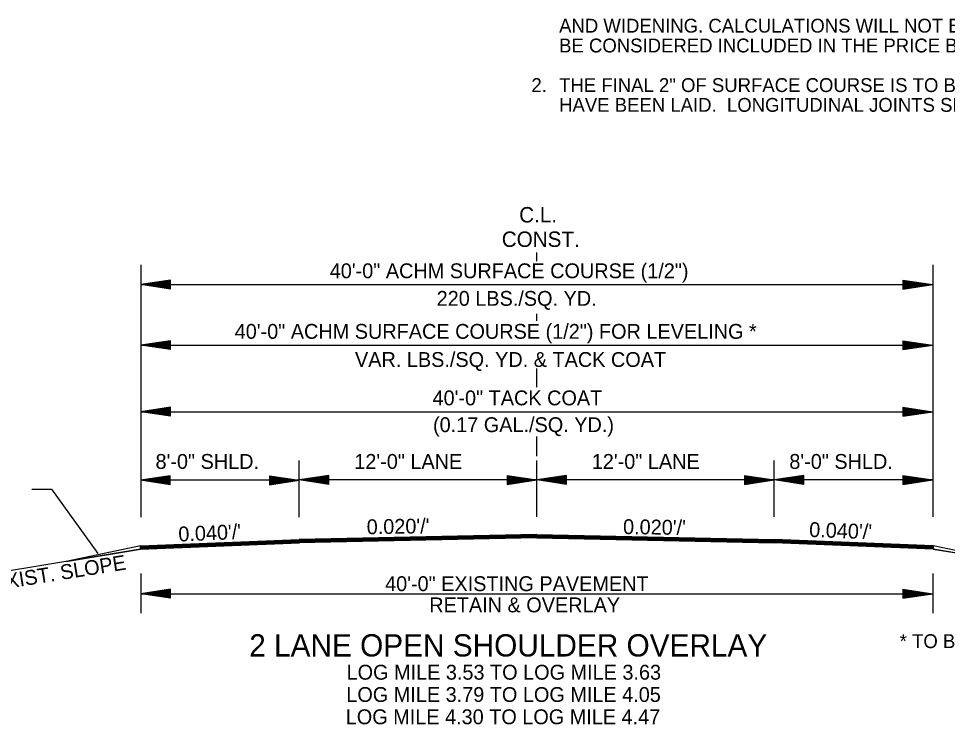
# Model space of a CAD drawing. Extents: x 544199 to 1930787, y -1968972 to 596640.
# Drawn here: x 551718.3 to 552187.5, y -1946877.6 to -1946521.1 of the extents above; entities that cross this region are included whole.
import ezdxf

# ---------------------------------------------------------------- set-up
doc = ezdxf.new("R2010")
doc.units = 0
for name, color, linetype in [('R_Border Notes', 7, 'Continuous'), ('R_Border Prem', 7, 'Continuous'), ('R_Draft', 7, 'Continuous')]:
    doc.layers.add(name, color=color, linetype=linetype)

msp = doc.modelspace()

# ---------------------------------------------------------------- linework, layer by layer
at = {"layer": 'R_Draft'}
for p, q in [((551980.07, -1946643.68), (551980.07, -1946639.27)), ((551780.07, -1946645.52), (551780.07, -1946772.95)), ((551795.07, -1946653.19), (551780.07, -1946655.44)), ((551780.07, -1946655.44), (552180.07, -1946655.44)), ((551795.07, -1946657.69), (551780.07, -1946655.44)), ((551795.07, -1946653.56), (551782.58, -1946655.44)), ((551795.07, -1946657.31), (551782.58, -1946655.44)), ((551795.07, -1946653.95), (551785.16, -1946655.44)), ((551795.07, -1946656.93), (551785.16, -1946655.44)), ((551795.07, -1946654.32), (551787.65, -1946655.44)), ((551795.07, -1946656.56), (551787.65, -1946655.44)), ((551795.07, -1946654.7), (551790.2, -1946655.44)), ((551795.07, -1946656.17), (551790.2, -1946655.44)), ((551795.07, -1946655.09), (551792.7, -1946655.44)), ((551795.07, -1946655.79), (551792.7, -1946655.44)), ((551795.07, -1946657.69), (551795.07, -1946653.19)), ((552165.07, -1946653.19), (552180.07, -1946655.44)), ((552165.07, -1946653.19), (552165.07, -1946657.69)), ((552165.07, -1946653.56), (552177.57, -1946655.44)), ((552165.07, -1946653.95), (552174.99, -1946655.44)), ((552165.07, -1946654.32), (552172.49, -1946655.44)), ((552165.07, -1946654.71), (552169.95, -1946655.44)), ((552165.07, -1946655.09), (552167.44, -1946655.44)), ((552165.07, -1946657.69), (552180.07, -1946655.44)), ((552165.07, -1946656.17), (552169.95, -1946655.44)), ((552165.07, -1946656.93), (552174.99, -1946655.44)), ((552165.07, -1946657.31), (552177.57, -1946655.44)), ((552165.07, -1946656.56), (552172.49, -1946655.44)), ((552165.07, -1946655.79), (552167.44, -1946655.44)), ((551980.07, -1946673.81), (551980.07, -1946670.14)), ((551795.07, -1946683.79), (551780.07, -1946686.04)), ((551795.07, -1946688.29), (551795.07, -1946683.79)), ((552165.07, -1946683.79), (552180.07, -1946686.04)), ((552165.07, -1946683.79), (552165.07, -1946688.29)), ((551780.07, -1946686.04), (552180.07, -1946686.04)), ((551795.07, -1946688.29), (551780.07, -1946686.04)), ((551795.07, -1946684.16), (551782.58, -1946686.04)), ((551795.07, -1946687.91), (551782.58, -1946686.04)), ((551795.07, -1946684.54), (551785.16, -1946686.04)), ((551795.07, -1946687.53), (551785.16, -1946686.04)), ((551795.07, -1946684.92), (551787.65, -1946686.04)), ((551795.07, -1946687.15), (551787.65, -1946686.04)), ((551795.07, -1946685.3), (551790.2, -1946686.04)), ((551795.07, -1946686.76), (551790.2, -1946686.04)), ((551795.07, -1946685.68), (551792.7, -1946686.04)), ((551795.07, -1946686.39), (551792.7, -1946686.04)), ((552165.07, -1946684.16), (552177.57, -1946686.04)), ((552165.07, -1946684.54), (552174.99, -1946686.04)), ((552165.07, -1946684.92), (552172.49, -1946686.04)), ((552165.07, -1946685.31), (552169.95, -1946686.04)), ((552165.07, -1946685.68), (552167.44, -1946686.04)), ((552165.07, -1946688.29), (552180.07, -1946686.04)), ((552165.07, -1946686.77), (552169.95, -1946686.04)), ((552165.07, -1946687.53), (552174.99, -1946686.04)), ((552165.07, -1946687.91), (552177.57, -1946686.04)), ((552165.07, -1946687.15), (552172.49, -1946686.04)), ((552165.07, -1946686.39), (552167.44, -1946686.04)), ((551980.07, -1946707.17), (551980.07, -1946697.86)), ((551795.07, -1946717.39), (551780.07, -1946719.64)), ((551780.07, -1946719.64), (552180.07, -1946719.64)), ((551795.07, -1946721.89), (551780.07, -1946719.64)), ((551795.07, -1946717.76), (551782.58, -1946719.64)), ((551795.07, -1946721.51), (551782.58, -1946719.64)), ((551795.07, -1946718.14), (551785.16, -1946719.64)), ((551795.07, -1946721.13), (551785.16, -1946719.64)), ((551795.07, -1946718.52), (551787.65, -1946719.64)), ((551795.07, -1946720.75), (551787.65, -1946719.64)), ((551795.07, -1946718.9), (551790.2, -1946719.64)), ((551795.07, -1946720.36), (551790.2, -1946719.64)), ((551795.07, -1946719.28), (551792.7, -1946719.64)), ((551795.07, -1946719.99), (551792.7, -1946719.64)), ((551795.07, -1946721.89), (551795.07, -1946717.39)), ((552165.07, -1946717.39), (552180.07, -1946719.64)), ((552165.07, -1946717.39), (552165.07, -1946721.89)), ((552165.07, -1946717.76), (552177.57, -1946719.64)), ((552165.07, -1946718.14), (552174.99, -1946719.64)), ((552165.07, -1946718.52), (552172.49, -1946719.64)), ((552165.07, -1946718.91), (552169.95, -1946719.64)), ((552165.07, -1946719.28), (552167.44, -1946719.64)), ((552165.07, -1946721.89), (552180.07, -1946719.64)), ((552165.07, -1946720.37), (552169.95, -1946719.64)), ((552165.07, -1946721.13), (552174.99, -1946719.64)), ((552165.07, -1946721.51), (552177.57, -1946719.64)), ((552165.07, -1946720.75), (552172.49, -1946719.64)), ((552165.07, -1946719.99), (552167.44, -1946719.64)), ((551980.07, -1946742.1), (551980.07, -1946732.23)), ((551860.07, -1946772.78), (551860.07, -1946744.23)), ((551860.07, -1946772.95), (551860.07, -1946744.23)), ((551980.07, -1946772.78), (551980.07, -1946744.23)), ((552100, -1946754.12), (552100, -1946744.23)), ((552100, -1946772.78), (552100, -1946744.23)), ((551794.81, -1946752.04), (551779.81, -1946754.29)), ((551794.81, -1946756.54), (551779.81, -1946754.29)), ((551860.07, -1946754.29), (551780.07, -1946754.29)), ((551794.81, -1946752.41), (551782.32, -1946754.29)), ((551794.81, -1946756.16), (551782.32, -1946754.29)), ((551794.81, -1946752.8), (551784.9, -1946754.29)), ((551794.81, -1946755.78), (551784.9, -1946754.29)), ((551794.81, -1946753.17), (551787.39, -1946754.29)), ((551794.81, -1946755.41), (551787.39, -1946754.29)), ((551794.81, -1946753.55), (551789.94, -1946754.29)), ((551794.81, -1946755.02), (551789.94, -1946754.29)), ((551794.81, -1946753.94), (551792.44, -1946754.29)), ((551794.81, -1946754.64), (551792.44, -1946754.29)), ((551794.81, -1946756.54), (551794.81, -1946752.04)), ((551845.07, -1946752.04), (551860.07, -1946754.29)), ((551845.07, -1946752.04), (551845.07, -1946756.54)), ((551845.07, -1946752.41), (551857.57, -1946754.29)), ((551845.07, -1946752.8), (551854.99, -1946754.29)), ((551845.07, -1946753.17), (551852.49, -1946754.29)), ((551845.07, -1946753.56), (551849.95, -1946754.29)), ((551845.07, -1946753.94), (551847.44, -1946754.29)), ((551845.07, -1946756.54), (551860.07, -1946754.29)), ((551845.07, -1946755.02), (551849.95, -1946754.29)), ((551845.07, -1946755.78), (551854.99, -1946754.29)), ((551845.07, -1946756.16), (551857.57, -1946754.29)), ((551845.07, -1946755.41), (551852.49, -1946754.29)), ((551845.07, -1946754.64), (551847.44, -1946754.29)), ((551875.07, -1946751.87), (551860.07, -1946754.12)), ((551980.07, -1946754.12), (551860.07, -1946754.12)), ((551875.07, -1946756.37), (551860.07, -1946754.12)), ((551875.07, -1946752.24), (551862.58, -1946754.12)), ((551875.07, -1946755.99), (551862.58, -1946754.12)), ((551875.07, -1946752.63), (551865.16, -1946754.12)), ((551875.07, -1946755.61), (551865.16, -1946754.12)), ((551875.07, -1946753), (551867.65, -1946754.12)), ((551875.07, -1946755.24), (551867.65, -1946754.12)), ((551875.07, -1946753.38), (551870.2, -1946754.12)), ((551875.07, -1946754.85), (551870.2, -1946754.12)), ((551875.07, -1946753.77), (551872.7, -1946754.12)), ((551875.07, -1946754.47), (551872.7, -1946754.12)), ((551875.07, -1946756.37), (551875.07, -1946751.87)), ((551965.07, -1946751.87), (551980.07, -1946754.12)), ((551965.07, -1946751.87), (551965.07, -1946756.37)), ((551965.07, -1946752.24), (551977.57, -1946754.12)), ((551965.07, -1946752.63), (551974.99, -1946754.12)), ((551965.07, -1946753), (551972.49, -1946754.12)), ((551965.07, -1946753.39), (551969.95, -1946754.12)), ((551965.07, -1946753.77), (551967.44, -1946754.12)), ((551965.07, -1946756.37), (551980.07, -1946754.12)), ((551965.07, -1946754.85), (551969.95, -1946754.12)), ((551965.07, -1946755.61), (551974.99, -1946754.12)), ((551965.07, -1946755.99), (551977.57, -1946754.12)), ((551965.07, -1946755.24), (551972.49, -1946754.12)), ((551965.07, -1946754.47), (551967.44, -1946754.12)), ((551995.07, -1946751.87), (551980.07, -1946754.12)), ((552100.07, -1946754.12), (551980.07, -1946754.12)), ((551995.07, -1946756.37), (551980.07, -1946754.12)), ((551995.07, -1946752.24), (551982.58, -1946754.12)), ((551995.07, -1946755.99), (551982.58, -1946754.12)), ((551995.07, -1946752.63), (551985.16, -1946754.12)), ((551995.07, -1946755.61), (551985.16, -1946754.12)), ((551995.07, -1946753), (551987.65, -1946754.12)), ((551995.07, -1946755.24), (551987.65, -1946754.12)), ((551995.07, -1946753.38), (551990.2, -1946754.12)), ((551995.07, -1946754.85), (551990.2, -1946754.12)), ((551995.07, -1946753.77), (551992.7, -1946754.12)), ((551995.07, -1946754.47), (551992.7, -1946754.12)), ((551995.07, -1946756.37), (551995.07, -1946751.87)), ((552085, -1946751.87), (552100, -1946754.12)), ((552085, -1946751.87), (552085, -1946756.37)), ((552085, -1946752.24), (552097.49, -1946754.12)), ((552085, -1946752.63), (552094.91, -1946754.12)), ((552085, -1946753), (552092.42, -1946754.12)), ((552085, -1946753.39), (552089.87, -1946754.12)), ((552085, -1946753.77), (552087.37, -1946754.12)), ((552085, -1946756.37), (552100, -1946754.12)), ((552085, -1946754.85), (552089.87, -1946754.12)), ((552085, -1946755.61), (552094.91, -1946754.12)), ((552085, -1946755.99), (552097.49, -1946754.12)), ((552085, -1946755.24), (552092.42, -1946754.12)), ((552085, -1946754.47), (552087.37, -1946754.12)), ((552115, -1946751.87), (552100, -1946754.12)), ((552100, -1946772.78), (552100, -1946754.12)), ((552115, -1946756.37), (552100, -1946754.12)), ((552180.07, -1946754.12), (552100.07, -1946754.12)), ((552115, -1946752.24), (552102.5, -1946754.12)), ((552115, -1946755.99), (552102.5, -1946754.12)), ((552115, -1946752.63), (552105.08, -1946754.12)), ((552115, -1946755.61), (552105.08, -1946754.12)), ((552115, -1946753), (552107.58, -1946754.12)), ((552115, -1946755.24), (552107.58, -1946754.12)), ((552115, -1946753.38), (552110.12, -1946754.12)), ((552115, -1946754.85), (552110.12, -1946754.12)), ((552115, -1946753.77), (552112.63, -1946754.12)), ((552115, -1946754.47), (552112.63, -1946754.12)), ((552115, -1946756.37), (552115, -1946751.87)), ((552165.07, -1946751.87), (552180.07, -1946754.12)), ((552165.07, -1946751.87), (552165.07, -1946756.37)), ((552165.07, -1946752.24), (552177.57, -1946754.12)), ((552165.07, -1946752.63), (552174.99, -1946754.12)), ((552165.07, -1946753), (552172.49, -1946754.12)), ((552165.07, -1946753.39), (552169.95, -1946754.12)), ((552165.07, -1946753.77), (552167.44, -1946754.12)), ((552165.07, -1946756.37), (552180.07, -1946754.12)), ((552165.07, -1946754.85), (552169.95, -1946754.12)), ((552165.07, -1946755.61), (552174.99, -1946754.12)), ((552165.07, -1946755.99), (552177.57, -1946754.12)), ((552165.07, -1946755.24), (552172.49, -1946754.12)), ((552165.07, -1946754.47), (552167.44, -1946754.12)), ((551980.07, -1946781.72), (551860.07, -1946784.12)), ((551980.08, -1946782.02), (551860.08, -1946784.42)), ((551980.08, -1946782.32), (551860.08, -1946784.72)), ((551980.06, -1946782.32), (552100.06, -1946784.72)), ((551980.07, -1946781.72), (552100.07, -1946784.12)), ((551980.07, -1946782.02), (552100.07, -1946784.42)), ((551779.81, -1946787.34), (551860.07, -1946784.12)), ((551779.81, -1946787.64), (551860.08, -1946784.42)), ((551779.81, -1946787.94), (551860.1, -1946784.72)), ((551779.81, -1946788.24), (551860.11, -1946785.02)), ((551779.81, -1946788.54), (551860.12, -1946785.32)), ((551779.81, -1946788.84), (551860.13, -1946785.62)), ((551779.81, -1946789.04), (551860.14, -1946785.82)), ((551980.09, -1946782.62), (551860.09, -1946785.02)), ((551980.1, -1946782.92), (551860.1, -1946785.32)), ((551980.1, -1946783.22), (551860.1, -1946785.62)), ((551980.11, -1946783.42), (551860.11, -1946785.82)), ((551980.04, -1946783.22), (552100.04, -1946785.62)), ((551980.04, -1946783.42), (552100.04, -1946785.82)), ((551980.05, -1946782.62), (552100.05, -1946785.02)), ((551980.05, -1946782.92), (552100.05, -1946785.32)), ((552180.33, -1946789.04), (552100, -1946785.82)), ((552180.33, -1946788.84), (552100.01, -1946785.62)), ((552180.33, -1946788.54), (552100.02, -1946785.32)), ((552180.33, -1946788.24), (552100.04, -1946785.02)), ((552180.33, -1946787.94), (552100.05, -1946784.72)), ((552180.33, -1946787.64), (552100.06, -1946784.42)), ((552180.33, -1946787.34), (552100.07, -1946784.12)), ((551779.81, -1946789.04), (551679.74, -1946805.71)), ((551779.81, -1946787.34), (551742.32, -1946795.28)), ((551742.32, -1946795.28), (551779.81, -1946789.04)), ((551779.81, -1946789.04), (551779.81, -1946787.34)), ((551779.81, -1946789.04), (551779.81, -1946787.34)), ((551779.81, -1946789.04), (551779.81, -1946787.34)), ((551779.81, -1946789.04), (551779.81, -1946789.04)), ((552180.33, -1946789.04), (552180.33, -1946787.34)), ((552180.33, -1946787.34), (552180.33, -1946789.04)), ((552219.58, -1946795.57), (552180.33, -1946787.34)), ((552180.33, -1946787.34), (552180.33, -1946789.04)), ((552180.33, -1946789.04), (552180.33, -1946787.34)), ((552280.4, -1946805.71), (552180.33, -1946789.04)), ((552180.33, -1946789.04), (552180.33, -1946789.04)), ((552180.33, -1946789.04), (552219.58, -1946795.57)), ((551780.07, -1946801.33), (551780.07, -1946821.33)), ((552180.07, -1946801.33), (552180.07, -1946821.33)), ((551795.07, -1946809.33), (551780.07, -1946811.58)), ((551795.07, -1946809.71), (551782.58, -1946811.58)), ((551795.07, -1946810.09), (551785.16, -1946811.58)), ((551795.07, -1946810.47), (551787.65, -1946811.58)), ((551795.07, -1946813.83), (551795.07, -1946809.33)), ((552165.07, -1946809.33), (552180.07, -1946811.58)), ((552165.07, -1946809.33), (552165.07, -1946813.83)), ((552165.07, -1946809.71), (552177.57, -1946811.58)), ((552165.07, -1946810.09), (552174.99, -1946811.58)), ((552165.07, -1946810.47), (552172.49, -1946811.58)), ((551780.07, -1946811.58), (552180.07, -1946811.58)), ((551795.07, -1946813.83), (551780.07, -1946811.58)), ((551795.07, -1946813.46), (551782.58, -1946811.58)), ((551795.07, -1946813.08), (551785.16, -1946811.58)), ((551795.07, -1946812.7), (551787.65, -1946811.58)), ((551795.07, -1946810.85), (551790.2, -1946811.58)), ((551795.07, -1946812.31), (551790.2, -1946811.58)), ((551795.07, -1946811.23), (551792.7, -1946811.58)), ((551795.07, -1946811.94), (551792.7, -1946811.58)), ((552165.07, -1946810.86), (552169.95, -1946811.58)), ((552165.07, -1946811.23), (552167.44, -1946811.58)), ((552165.07, -1946813.83), (552180.07, -1946811.58)), ((552165.07, -1946812.32), (552169.95, -1946811.58)), ((552165.07, -1946813.08), (552174.99, -1946811.58)), ((552165.07, -1946813.46), (552177.57, -1946811.58)), ((552165.07, -1946812.7), (552172.49, -1946811.58)), ((552165.07, -1946811.94), (552167.44, -1946811.58))]:
    msp.add_line(p, q, dxfattribs=at)
for points in [[(552180.07, -1946645.52), (552180.07, -1946772.78)], [(551724.96, -1946758.8), (551734.96, -1946758.8), (551758.29, -1946791.29)]]:
    msp.add_lwpolyline(points, dxfattribs=at)

# ---------------------------------------------------------------- texts
at = {"layer": 'R_Border Notes'}
for s, p in [('AND WIDENING. CALCULATIONS WILL NOT BE PAID FOR DIRECTLY, BUT PAYMENT SHALL', (551991.36, -1946528.18)), ('BE CONSIDERED INCLUDED IN THE PRICE BID FOR THE VARIOUS PAY ITEMS.', (551991.36, -1946538.18)), ('2.', (551977.36, -1946558.18)), ('THE FINAL 2" OF SURFACE COURSE IS TO BE PLACED AFTER ALL OTHER COURSES', (551991.36, -1946558.18)), ('HAVE BEEN LAID.  LONGITUDINAL JOINTS SHALL BE AT LANE LINES.', (551991.36, -1946568.18))]:
    msp.add_text(s, height=7, dxfattribs=at).set_placement(p)
at = {"layer": 'R_Border Prem'}
msp.add_text('* TO BE USED IF AND WHERE DIRECTED BY THE ENGINEER.', height=7, dxfattribs=at).set_placement((552163.42, -1946839.04))
at = {"layer": 'R_Draft'}
for s, height, p in [('C.L.', 7.8, (551971.18, -1946624.07)), ('CONST.', 7.8, (551962.39, -1946636.43)), ('40\'-0" ACHM SURFACE COURSE (1/2")', 7.5, (551875.48, -1946652.22)), ('220 LBS./SQ. YD. ', 7.5, (551929.49, -1946666.16)), ('40\'-0" ACHM SURFACE COURSE (1/2") FOR LEVELING *', 7.5, (551827.47, -1946682.82)), ('VAR. LBS./SQ. YD. & TACK COAT', 7.5, (551888.24, -1946697.03)), ('40\'-0" TACK COAT', 7.5, (551927.42, -1946716.42)), ('(0.17 GAL./SQ. YD.)', 7.5, (551927.66, -1946729.96)), ('8\'-0" SHLD.', 7.5, (551787.46, -1946748.52)), ('12\'-0" LANE', 7.5, (551887.89, -1946748.52)), ('12\'-0" LANE', 7.5, (552007.85, -1946748.52)), ('8\'-0" SHLD.', 7.5, (552107.65, -1946748.52)), ('40\'-0" EXISTING PAVEMENT', 7.5, (551903.45, -1946810.26)), ('RETAIN & OVERLAY', 7.5, (551925.74, -1946820.98)), ('2 LANE OPEN SHOULDER OVERLAY', 11.25, (551834.8, -1946843.29)), ('LOG MILE 3.53 TO LOG MILE 3.63', 7.5, (551883.99, -1946854.99)), ('LOG MILE 3.79 TO LOG MILE 4.05', 7.5, (551883.87, -1946866.24)), ('LOG MILE 4.30 TO LOG MILE 4.47', 7.5, (551883.58, -1946877.49))]:
    msp.add_text(s, height=height, dxfattribs=at).set_placement(p)
for s, rotation, p in [("0.040'/'", 2.448, (551799.16, -1946785.24)), ("0.020'/'", 0.8719, (551894.21, -1946781.55)), ("0.020'/'", 359.164, (552023.62, -1946781.43)), ("0.040'/'", 357.8168, (552117.58, -1946782.86)), ('EXIST. SLOPE', 9.1534, (551705.83, -1946810.12))]:
    msp.add_text(s, height=7.5, rotation=rotation, dxfattribs=at).set_placement(p)

doc.saveas('drawing.dxf')
